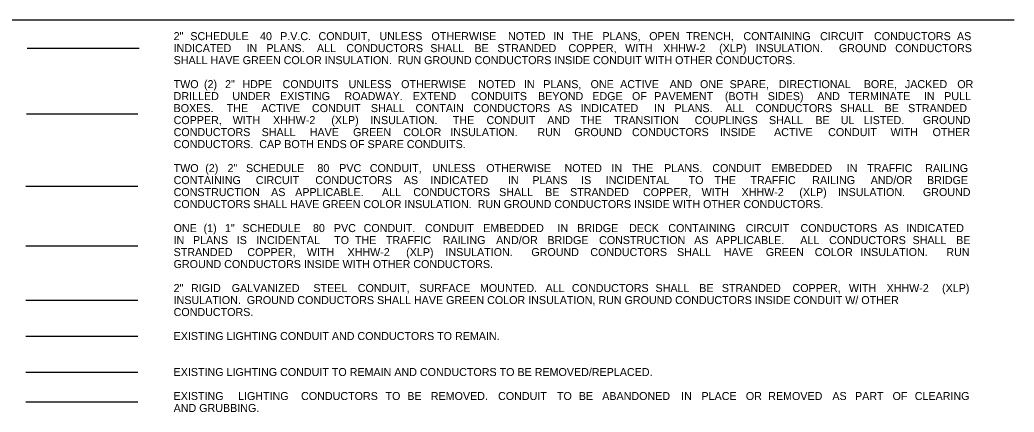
# Model space of a CAD drawing. Extents: x -1452 to -654, y -278 to 245.
# Drawn here: x -1026.7 to -654.2, y 93.4 to 240.5 of the extents above; entities that cross this region are included whole.
import ezdxf

# ---------------------------------------------------------------- set-up
doc = ezdxf.new("R2010")
doc.units = 0
for name, color, linetype in [('ConduitAG', 7, 'Continuous'), ('ConduitBM', 7, 'Continuous'), ('ConduitDB', 7, 'Continuous'), ('ConduitJB', 7, 'Continuous'), ('ConduitOT', 7, 'Continuous'), ('Miscellaneous3', 7, 'Continuous'), ('Miscellaneous8', 7, 'Continuous'), ('SheetBorder_dp', 7, 'Continuous')]:
    doc.layers.add(name, color=color, linetype=linetype)

msp = doc.modelspace()

# ---------------------------------------------------------------- linework, layer by layer
at = {"layer": 'ConduitAG'}
for p, q in [((-1024.44, 135.39), (-982.49, 135.39)), ((-1024.44, 121.9), (-982.49, 121.9)), ((-1024.44, 108.36), (-982.49, 108.36))]:
    msp.add_line(p, q, dxfattribs=at)
at = {"layer": 'ConduitBM'}
msp.add_line((-1024.45, 155.76), (-982.5, 155.76), dxfattribs=at)
at = {"layer": 'ConduitDB'}
msp.add_line((-1024.44, 178.13), (-982.49, 178.13), dxfattribs=at)
at = {"layer": 'ConduitJB'}
msp.add_line((-1024.19, 205.33), (-982.49, 205.33), dxfattribs=at)
at = {"layer": 'ConduitOT'}
msp.add_line((-1023.94, 229.93), (-981.99, 229.93), dxfattribs=at)
at = {"layer": 'Miscellaneous3'}
msp.add_line((-1424.17, 240.54), (-654.17, 240.54), dxfattribs=at)
at = {"layer": 'Miscellaneous8'}
msp.add_line((-1024.44, 97.21), (-982.49, 97.21), dxfattribs=at)

# ---------------------------------------------------------------- texts
at = {"layer": 'SheetBorder_dp'}
for s, p in [('2" ', (-969.09, 232.93)), ('SCHEDULE ', (-962.82, 232.93)), ('40 ', (-936.71, 232.93)), ('P.V.C. ', (-929.17, 232.93)), ('CONDUIT, ', (-914.8, 232.93)), ('UNLESS ', (-891.98, 232.93)), ('OTHERWISE ', (-872.49, 232.93)), ('NOTED ', (-843.8, 232.93)), ('IN ', (-826.87, 232.93)), ('THE ', (-819.81, 232.93)), ('PLANS, ', (-808.41, 232.93)), ('OPEN ', (-790.88, 232.93)), ('TRENCH, ', (-777.03, 232.93)), ('CONTAINING ', (-755.59, 232.93)), ('CIRCUIT ', (-726.87, 232.93)), ('CONDUCTORS ', (-706.66, 232.93)), ('AS ', (-675.58, 232.93)), ('INDICATED ', (-969.09, 228.43)), ('IN ', (-941.76, 228.43)), ('PLANS. ', (-934.32, 228.43)), (' ALL ', (-916.53, 228.43)), ('CONDUCTORS ', (-904.39, 228.43)), ('SHALL ', (-872.92, 228.43)), ('BE ', (-856.4, 228.43)), ('STRANDED ', (-847.78, 228.43)), ('COPPER, ', (-821.16, 228.43)), ('WITH ', (-799.89, 228.43)), ('XHHW-2 ', (-785.65, 228.43)), ('(XLP) ', (-764.7, 228.43)), ('INSULATION. ', (-750.97, 228.43)), (' GROUND ', (-720.93, 228.43)), ('CONDUCTORS ', (-698.73, 228.43)), ('SHALL HAVE GREEN COLOR INSULATION.  RUN GROUND CONDUCTORS INSIDE CONDUIT WITH OTHER CONDUCTORS. ', (-969.09, 223.93)), ('TWO ', (-969.09, 214.93)), ('(2) ', (-957.71, 214.93)), ('2" ', (-949.81, 214.93)), ('HDPE ', (-943.35, 214.93)), ('CONDUITS ', (-928.26, 214.93)), ('UNLESS ', (-903.53, 214.93)), ('OTHERWISE ', (-883.84, 214.93)), ('NOTED ', (-854.97, 214.93)), ('IN ', (-837.84, 214.93)), ('PLANS, ', (-830.59, 214.93)), ('ONE ', (-812.87, 214.93)), ('ACTIVE ', (-801.77, 214.93)), ('AND ', (-783.22, 214.93)), ('ONE ', (-771.86, 214.93)), ('SPARE, ', (-760.77, 214.93)), ('DIRECTIONAL ', (-742.39, 214.93)), ('BORE, ', (-710.5, 214.93)), ('JACKED ', (-695.08, 214.93)), ('OR ', (-675.47, 214.93)), ('DRILLED ', (-969.09, 210.43)), ('UNDER ', (-947.09, 210.43)), ('EXISTING ', (-929.23, 210.43)), ('ROADWAY. ', (-905.08, 210.43)), (' EXTEND ', (-880.59, 210.43)), ('CONDUITS ', (-857.65, 210.43)), ('BEYOND ', (-832.55, 210.43)), ('EDGE ', (-812.21, 210.43)), ('OF ', (-797.34, 210.43)), ('PAVEMENT ', (-789.01, 210.43)), ('(BOTH ', (-762.55, 210.43)), ('SIDES) ', (-746.45, 210.43)), ('AND ', (-727.94, 210.43)), ('TERMINATE ', (-716.21, 210.43)), ('IN ', (-687.99, 210.43)), ('PULL ', (-680.37, 210.43)), ('BOXES. ', (-969.09, 205.93)), (' THE ', (-950.31, 205.93)), ('ACTIVE ', (-936.22, 205.93)), ('CONDUIT ', (-917.27, 205.93)), ('SHALL ', (-895.18, 205.93)), ('CONTAIN ', (-878.45, 205.93)), ('CONDUCTORS ', (-856.8, 205.93)), ('AS ', (-825.13, 205.93)), ('INDICATED ', (-816.61, 205.93)), ('IN ', (-789.09, 205.93)), ('PLANS. ', (-781.44, 205.93)), (' ALL ', (-763.45, 205.93)), ('CONDUCTORS ', (-751.1, 205.93)), ('SHALL ', (-719.43, 205.93)), ('BE ', (-702.7, 205.93)), ('STRANDED ', (-693.88, 205.93)), ('COPPER, ', (-969.09, 201.43)), ('WITH ', (-946.95, 201.43)), ('XHHW-2 ', (-931.83, 201.43)), ('(XLP) ', (-910.01, 201.43)), ('INSULATION. ', (-895.41, 201.43)), ('THE ', (-864.5, 201.43)), ('CONDUIT ', (-851.85, 201.43)), ('AND ', (-829.09, 201.43)), ('THE ', (-816.67, 201.43)), ('TRANSITION ', (-804.02, 201.43)), ('COUPLINGS ', (-773.86, 201.43)), ('SHALL ', (-746.03, 201.43)), ('BE ', (-728.63, 201.43)), ('UL ', (-719.14, 201.43)), ('LISTED. ', (-710.48, 201.43)), (' GROUND ', (-689.46, 201.43)), ('CONDUCTORS ', (-969.09, 196.93)), ('SHALL ', (-936.12, 196.93)), ('HAVE ', (-918.09, 196.93)), ('GREEN ', (-901.86, 196.93)), ('COLOR ', (-883.05, 196.93)), ('INSULATION. ', (-865.42, 196.93)), (' RUN ', (-833.88, 196.93)), ('GROUND ', (-818.95, 196.93)), ('CONDUCTORS ', (-797.35, 196.93)), ('INSIDE ', (-764.38, 196.93)), ('ACTIVE ', (-744.11, 196.93)), ('CONDUIT ', (-723.85, 196.93)), ('WITH ', (-700.46, 196.93)), ('OTHER ', (-684.72, 196.93)), ('CONDUCTORS.  CAP BOTH ENDS OF SPARE CONDUITS.', (-969.09, 192.43)), ('TWO ', (-969.09, 183.43)), ('(2) ', (-957.25, 183.43)), ('2" ', (-948.89, 183.43)), ('SCHEDULE ', (-941.98, 183.43)), ('80 ', (-915.22, 183.43)), ('PVC ', (-907.04, 183.43)), ('CONDUIT, ', (-895.57, 183.43)), ('UNLESS ', (-872.1, 183.43)), ('OTHERWISE ', (-851.96, 183.43)), ('NOTED ', (-822.63, 183.43)), ('IN ', (-805.05, 183.43)), ('THE ', (-797.34, 183.43)), ('PLANS. ', (-785.3, 183.43)), ('CONDUIT ', (-767.25, 183.43)), ('EMBEDDED ', (-745.1, 183.43)), ('IN ', (-716.91, 183.43)), ('TRAFFIC ', (-709.2, 183.43)), ('RAILING ', (-687.47, 183.43)), ('CONTAINING ', (-969.09, 178.93)), ('CIRCUIT ', (-938.3, 178.93)), ('CONDUCTORS ', (-916.01, 178.93)), ('AS ', (-882.85, 178.93)), ('INDICATED ', (-872.85, 178.93)), ('IN ', (-843.83, 178.93)), ('PLANS ', (-834.69, 178.93)), ('IS ', (-816.4, 178.93)), ('INCIDENTAL ', (-807.2, 178.93)), ('TO ', (-776.12, 178.93)), ('THE ', (-766.44, 178.93)), ('TRAFFIC ', (-752.97, 178.93)), ('RAILING ', (-729.81, 178.93)), ('AND/OR ', (-707.91, 178.93)), ('BRIDGE ', (-686.81, 178.93)), ('CONSTRUCTION ', (-969.09, 174.43)), ('AS ', (-932.56, 174.43)), ('APPLICABLE. ', (-923.54, 174.43)), (' ALL ', (-892.14, 174.43)), ('CONDUCTORS ', (-879.29, 174.43)), ('SHALL ', (-847.12, 174.43)), ('BE ', (-829.88, 174.43)), ('STRANDED ', (-820.55, 174.43)), ('COPPER, ', (-793.23, 174.43)), ('WITH ', (-771.25, 174.43)), ('XHHW-2 ', (-756.3, 174.43)), ('(XLP) ', (-734.65, 174.43)), ('INSULATION. ', (-720.21, 174.43)), (' GROUND ', (-689.46, 174.43)), ('CONDUCTORS SHALL HAVE GREEN COLOR INSULATION.  RUN GROUND CONDUCTORS INSIDE WITH OTHER CONDUCTORS.  ', (-969.09, 169.93)), ('ONE ', (-969.09, 160.93)), ('(1) ', (-957.88, 160.93)), ('1" ', (-949.86, 160.93)), ('SCHEDULE ', (-943.29, 160.93)), ('80 ', (-916.87, 160.93)), ('PVC ', (-909.03, 160.93)), ('CONDUIT. ', (-897.9, 160.93)), ('CONDUIT ', (-874.91, 160.93)), ('EMBEDDED ', (-853.11, 160.93)), ('IN ', (-825.26, 160.93)), ('BRIDGE ', (-817.89, 160.93)), ('DECK ', (-798.42, 160.93)), ('CONTAINING ', (-783.74, 160.93)), ('CIRCUIT ', (-754.72, 160.93)), ('CONDUCTORS ', (-734.21, 160.93)), ('AS ', (-702.82, 160.93)), ('INDICATED ', (-694.59, 160.93)), ('IN ', (-969.09, 156.43)), ('PLANS ', (-961.84, 156.43)), ('IS ', (-945.43, 156.43)), ('INCIDENTAL ', (-938.11, 156.43)), ('TO ', (-908.93, 156.43)), ('THE ', (-901.13, 156.43)), ('TRAFFIC ', (-889.54, 156.43)), ('RAILING ', (-868.27, 156.43)), ('AND/OR ', (-848.25, 156.43)), ('BRIDGE ', (-829.04, 156.43)), ('CONSTRUCTION ', (-809.68, 156.43)), ('AS ', (-774.06, 156.43)), ('APPLICABLE. ', (-765.94, 156.43)), (' ALL ', (-735.43, 156.43)), ('CONDUCTORS ', (-723.49, 156.43)), ('SHALL ', (-692.22, 156.43)), ('BE ', (-675.88, 156.43)), ('STRANDED ', (-969.09, 151.93)), ('COPPER, ', (-941.47, 151.93)), ('WITH ', (-919.18, 151.93)), ('XHHW-2 ', (-903.93, 151.93)), ('(XLP) ', (-881.97, 151.93)), ('INSULATION. ', (-867.22, 151.93)), (' GROUND ', (-836.17, 151.93)), ('CONDUCTORS ', (-812.96, 151.93)), ('SHALL ', (-780.48, 151.93)), ('HAVE ', (-762.94, 151.93)), ('GREEN ', (-747.2, 151.93)), ('COLOR ', (-728.88, 151.93)), ('INSULATION. ', (-711.74, 151.93)), (' RUN ', (-680.69, 151.93)), ('GROUND CONDUCTORS INSIDE WITH OTHER CONDUCTORS.  ', (-969.09, 147.43)), ('(XLP) ', (-681.17, 138.43)), ('2" ', (-969.09, 138.43)), ('RIGID ', (-962.58, 138.43)), ('GALVANIZED ', (-947.32, 138.43)), ('STEEL ', (-916.74, 138.43)), ('CONDUIT, ', (-900.09, 138.43)), ('SURFACE ', (-877.04, 138.43)), ('MOUNTED. ', (-854.3, 138.43)), ('ALL ', (-829.75, 138.43)), ('CONDUCTORS ', (-819.86, 138.43)), ('SHALL ', (-788.53, 138.43)), ('BE ', (-772.15, 138.43)), ('STRANDED ', (-763.67, 138.43)), ('COPPER, ', (-737.2, 138.43)), ('WITH ', (-716.07, 138.43)), ('XHHW-2 ', (-701.97, 138.43)), ('INSULATION.  GROUND CONDUCTORS SHALL HAVE GREEN COLOR INSULATION, RUN GROUND CONDUCTORS INSIDE CONDUIT W/ OTHER ', (-969.09, 133.93)), ('CONDUCTORS.', (-969.09, 129.43)), ('EXISTING LIGHTING CONDUIT AND CONDUCTORS TO REMAIN.', (-969.09, 120.43)), ('EXISTING LIGHTING CONDUIT TO REMAIN AND CONDUCTORS TO BE REMOVED/REPLACED. ', (-969.09, 106.93)), ('EXISTING ', (-969.09, 97.93)), ('LIGHTING ', (-944.95, 97.93)), ('CONDUCTORS ', (-921.33, 97.93)), ('TO ', (-889.69, 97.93)), ('BE ', (-881.52, 97.93)), ('REMOVED. ', (-872.73, 97.93)), ('CONDUIT ', (-847.52, 97.93)), ('TO ', (-825.46, 97.93)), ('BE ', (-817.29, 97.93)), ('ABANDONED ', (-808.5, 97.93)), ('IN ', (-778.94, 97.93)), ('PLACE ', (-771.32, 97.93)), ('OR ', (-754.68, 97.93)), ('REMOVED ', (-746.3, 97.93)), ('AS ', (-722.27, 97.93)), ('PART ', (-713.78, 97.93)), ('OF ', (-699.71, 97.93)), ('CLEARING ', (-691.4, 97.93)), ('AND GRUBBING.', (-969.09, 93.43))]:
    msp.add_text(s, height=3, dxfattribs=at).set_placement(p)

doc.saveas('drawing.dxf')
